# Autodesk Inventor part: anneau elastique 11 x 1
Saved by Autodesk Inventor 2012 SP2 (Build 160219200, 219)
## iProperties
Created: 2013-04
Part Number: anneau elastique 11 x 1
Material: Default
Document SubType Name: Modeling
Designer: papa
Density: 1 g/cm^3
Mass: 0.0584203 g
Surface Area: 2.08022 cm^2
Volume: 0.0584203 cm^3
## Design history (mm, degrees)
node "anneau elastique 11 x 11"
node "anneau elastique 11 x 1"
node "Base1"
